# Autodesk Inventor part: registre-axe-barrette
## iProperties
Author: chr
Created: 2001-06
Part Number: registre-axe-barrette
Material: Par défaut
Document SubType Name: Modélisation
Designer: chr
Control State: 0
Master: False
Checked Out: False
PropertySet Name: Design Tracking Control
Shininess: 20.0
PropertySet Name: _Private Model Information
Length Units: 11269
Angle Units: 11286
Time Units: 11279
Mass Units: 11290
Length Display Precision: 3
Angle Display Precision: 2
Compacted: False
Density: 0.0
Volumn: 0.0
Area: 0.0
PropertySet Name: Model Information
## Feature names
1. Extrusion1
2. Extrusion2
